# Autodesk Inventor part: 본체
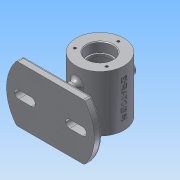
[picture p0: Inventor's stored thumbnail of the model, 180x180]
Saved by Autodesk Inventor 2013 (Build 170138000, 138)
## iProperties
Created: 2017-12
Part Number: 본체
Material: 알루미늄 6061
Document SubType Name: Modeling
Designer: Administrator
Density: 2.71 g/cm^3
Mass: 467.691 g
Surface Area: 486.469 cm^2
Volume: 172.58 cm^3
Author: Administrator
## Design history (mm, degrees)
sketch "스케치1"
  geometry: L1 (0, 35)-(30, 35); L2 (30, 35)-(30, 0); L3 (0, 0)-(0, 35); L4 (0, 0)-(30, 0); 1 further point
  constraints: 8 end point, 2 horizontal, 1 coincident, 1 parallel, 1 perpendicular
  dimensions: "d4" = 30 distance of L1.start L1.end; "d6" = 35 distance of L1.end L2.end
revolve "회전1" sketch "스케치1" stored, may be unused: angle "d5" = 90 deg
sketch "스케치2"
  geometry: C1 r 30 at (0, 0) reference; 1 further point
  constraints: 1 vertical alignment
  dimensions: "d7" = 23 distance of C1.centre point (0, 23)
hole "구멍1" sketch "스케치2" at (0, 23) diameter "d8" = 3.242; stored, may be unused: countersink angle "d12" = 90 deg, drill point angle "d14" = 118 deg; dims "d9" = 8, "d10" = 4, "d11" = 2, "d13" = 10
hole "구멍2" diameter "d20" = 50; stored, may be unused: countersink angle "d24" = 90 deg, drill point angle "d26" = 0 deg; dims "d18" = 10, "d19" = 10, "d21" = 8, "d22" = 4, "d23" = 2, "d25" = 20
hole "구멍3" diameter "d29" = 28; stored, may be unused: countersink angle "d33" = 90 deg, drill point angle "d35" = 0 deg; dims "d30" = 8, "d31" = 32, "d32" = 12, "d34" = 15, "d36" = 10, "d37" = 10
fillet "모깎기1" dims "d38" = 0.3
chamfer "모따기1" distance "d39" = 1; stored, may be unused: second distance "d40" = 2, angle "d41" = 45 deg
fillet "모깎기2" dims "d42" = 3
node "작업 평면1"
sketch "스케치3"
  geometry: C1 r 8 at (0, 0); 1 further point
  constraints: 1 centre point, 1 coincident
  dimensions: "d44" = 16 diameter of C1
extrude "돌출1" join sketch "스케치3" stored distance "d46" = 10; taper "d47" = 0 deg
hole "구멍4" diameter "d50" = 8; stored, may be unused: countersink angle "d54" = 90 deg, drill point angle "d56" = 0 deg; dims "d51" = 8, "d52" = 32, "d53" = 12, "d55" = 20, "d57" = 10, "d58" = 10
chamfer "모따기2" distance "d59" = 1; stored, may be unused: second distance "d60" = 2, angle "d61" = 45 deg
node "작업 평면2"
sketch "스케치4"
  geometry: L1 (0, 35)-(42.426, 35); L2 (0, -35)-(42.426, -35); L3 (24, -5)-(40, -5); L4 (24, 5)-(40, 5); L5 (0, 35)-(0, -35); A1 r 55 centre (0, 0) between (42.426, -35) and (42.426, 35); A2 r 5 centre (24, 0) between (24, 5) and (24, -5); A3 r 5 centre (40, 0) between (40, -5) and (40, 5); 2 further points
  constraints: 10 end point, 6 point on circle, 4 tangent, 3 centre point, 2 coincident, 2 horizontal alignment, 1 equal radius, 1 horizontal, 1 midpoint, 1 parallel, 1 vertical
  dimensions: "d66" = 55 radius of A1; "d67" = 16 distance of A3.centre A2.centre; "d68" = 70 distance of L1.start L2.start; "d69" = 5 radius of A2; "d70" = 24 distance of point (0, 0) A2.centre
extrude "돌출2" join sketch "스케치4" distance "d71" = 10; taper "d72" = 0 deg
sketch "스케치5"
  geometry: L1 (5, 15)-(5, -15); L2 (-5, -15)-(-5, 15); A1 r 55 centre (0, 0) between (-42.426, 35) and (-42.426, -35) reference; A2 r 5 centre (0, 15) between (5, 15) and (-5, 15); A3 r 5 centre (0, -15) between (-5, -15) and (5, -15)
  constraints: 5 end point, 4 point on circle, 4 tangent, 2 centre point, 2 vertical alignment, 1 parallel
  dimensions: "d73" = 30 distance of A3.centre A2.centre; "d75" = 5 radius of A2; "d76" = 15 distance of A2.centre A1.centre (= 0.5 x d73)
extrude "돌출3" join sketch "스케치5" stored distance "d77" = 10; taper "d78" = 0 deg
node "작업 평면3"
sketch "스케치6"
  geometry: L1 (-30, 35)-(30, 35) reference; 2 further points
  constraints: 1 other
  dimensions: "d80" = 35 distance from line of L1 point (0, 0); "d81" = 30 horizontal distance of L1.end point (0, 0)
feature "엠보싱1" sketch "스케치6" dims "d82" = 0.5, "d83" = 0
fillet "모깎기3" dims "d84" = 3
fillet "모깎기4" dims "d85" = 3
fillet "모깎기5" dims "d86" = 5
node "솔리드1"
pattern_circular "원형 패턴1" dims angle "d16" = 360 deg
mirror "대칭1"
mirror "대칭2"
other parameters: "d43" = 37, "d62" = -62, "d79" = 31
